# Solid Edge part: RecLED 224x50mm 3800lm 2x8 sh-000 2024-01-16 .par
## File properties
Author: jaroslaw.przewlocki
Template: iso metric part.par
Last saved by: jaroslaw.przewlocki
Revision: 2
Application: Solid Edge
Gęstość: 0,000 kg/m^3
Dokładność: 0,990
Username: jaroslaw.przewlocki
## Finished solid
Body 1: solid body, 1075 faces, 2765 edges, 1795 vertices.
  Faces by surface: plane 499, cylinder 412, torus 84, cone 44, spline 25, sphere 10, spun 1
  Edges by curve: line 1618, circle 610, curve on surface 331, ellipse 130, spline 76
Bounding box of the edges (mm; curved faces can reach further): 49.500 x 4.950 x 223.000, from (-24.75, -3.4504, -111.5) to (24.75, 1.5, 111.5).
Cylindrical faces by radius (mm): R0.05 x64, R0.1 x192, R0.199 x1, R0.2 x55, R0.2002 x2, R0.2169 x3, R0.25 x12, R0.3 x2, R0.3373 x3, R0.4 x8, R0.4006 x2, R0.4008 x2, R0.525 x2, R0.6 x12, R1 x7, R1.05 x16, R1.0894 x2, R1.0991 x4, R1.1 x14, R1.5342 x3, R1.5343 x1, R1.7456 x1, R1.75 x4
Conical faces (half-angle, radius in mm at the cone's reference point): 0.3913 deg R1.0968 x2, 0.447 deg R1.0952 x2, 0.464 deg R1.0955 x2, 0.5 deg R0.5056 x4, 0.5 deg R1.0082 x4, 1 deg R0.5511 x2, 10 deg R0.2132 x2, 10 deg R0.4132 x2, 15.6748 deg R1.1041 x1, 15.6751 deg R1.1041 x1, 15.7937 deg R1.1267 x1, 15.7938 deg R1.1267 x1, 18.4844 deg R1.0657 x4, 18.9316 deg R0.5099 x2, 19.4335 deg R0.5111 x2, 27.363 deg R0.6214 x2, 40.1747 deg R0.5201 x1, 40.1843 deg R0.5199 x1, 42.9201 deg R0.4919 x1, 42.9358 deg R0.4915 x1, 45 deg R0.575 x2, 45 deg R0.625 x4
Toroidal faces (ring radius, tube radius in mm): R-0.0731 r1.395 x16, R0.0958 r0.3997 x4, R0.1 r0.2 x1, R0.1075 r0.4 x2, R0.1101 r0.4001 x2, R0.1216 r0.4 x2, R0.1234 r0.4 x2, R0.1634 r0.2287 x1, R0.1641 r0.2287 x1, R0.3286 r0.2001 x1, R0.3322 r0.2 x1, R0.3702 r0.4 x2, R0.3818 r0.2 x2, R0.4163 r0.3984 x2, R0.4824 r0.2001 x1, R0.4952 r0.2 x1, R0.6009 r0.3968 x2, R0.6009 r0.3969 x2, R0.6235 r0.2 x1, R0.8 r0.2 x4, R0.8522 r0.3 x2, R0.9002 r0.2 x1, R0.9018 r0.2 x1, R0.9181 r0.2227 x2, R0.9197 r0.223 x1, R0.9199 r0.223 x1, R0.9663 r0.2263 x1, R0.9665 r0.2263 x1, R1.3 r0.2 x2, R1.327 r1.1 x2, R1.3271 r1.1 x2, R1.4708 r0.15 x16, R1.8741 r0.2175 x1, R1.8987 r0.2 x1
Spherical faces by radius (mm): R0.2 x8, R0.6 x2
Planar faces by outward normal: +x 81, +y 24, +z 81, -x 81, -y 42, -z 106, oblique 84
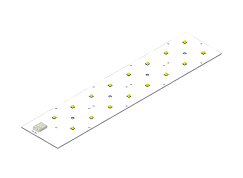
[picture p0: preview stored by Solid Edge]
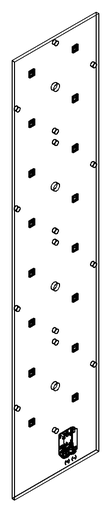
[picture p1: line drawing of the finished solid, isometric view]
